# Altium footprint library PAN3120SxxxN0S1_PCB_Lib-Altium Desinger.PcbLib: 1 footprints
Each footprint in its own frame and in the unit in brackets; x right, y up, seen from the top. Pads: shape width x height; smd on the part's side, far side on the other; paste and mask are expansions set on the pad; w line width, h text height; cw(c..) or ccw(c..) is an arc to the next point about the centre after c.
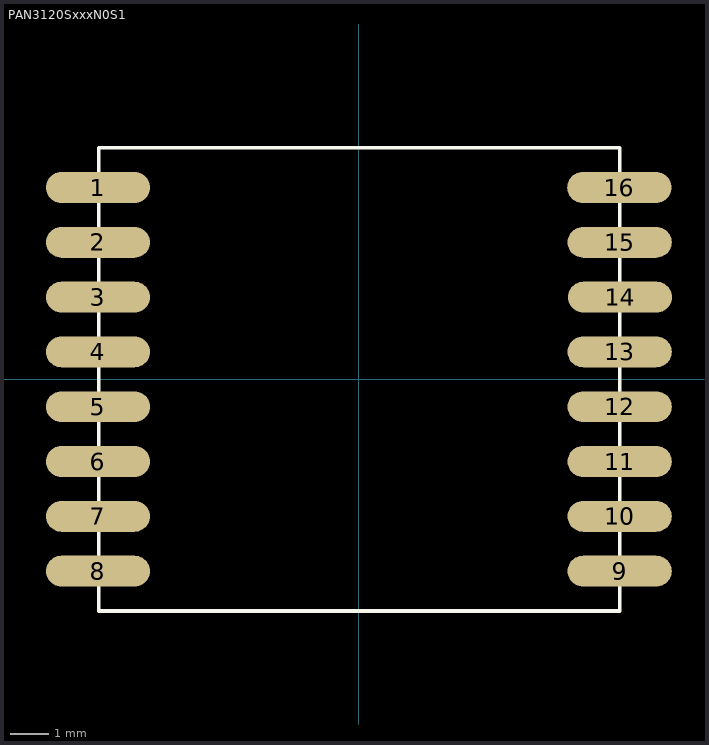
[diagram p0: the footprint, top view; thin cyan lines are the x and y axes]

## PAN3120SxxxN0S1 [mm]
pads (17):
  round 1 on Top Overlay: 1(-7.874,6.096)
  oval 2.7x0.8 smd: 1(-6.765,4.97) 2(-6.765,3.55) 3(-6.765,2.13) 4(-6.765,0.71) 5(-6.765,-0.71) 6(-6.765,-2.13) 7(-6.765,-3.55) 8(-6.765,-4.97) 9(6.755,-4.97) 10(6.755,-3.55) 11(6.755,-2.13) 12(6.755,-0.71) 13(6.755,0.71) 14(6.765,2.13) 15(6.755,3.55) 16(6.745,4.97)
Top Overlay:
  lines w0.1: -6.745,-6 -6.745,6 6.755,6 6.755,-6 -6.745,-6
3D body: height 0.25, standoff 0, extent -2.099,1.556 -2.099,1.556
